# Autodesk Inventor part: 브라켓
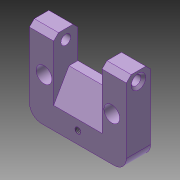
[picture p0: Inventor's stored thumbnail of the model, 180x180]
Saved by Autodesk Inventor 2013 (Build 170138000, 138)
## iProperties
Created: 2023-11
Part Number: 브라켓
Material: 강철, 연강
Document SubType Name: Modeling
Designer: mdu-01
Density: 1 g/cm^3
Author: mdu-01
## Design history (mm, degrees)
sketch "스케치1"
  geometry: L1 (0, 0)-(0, 10.407); L2 (-20, 5)-(-20, 34); L3 (-20, 34)-(-10, 34); L4 (-10, 34)-(-10, 20); L5 (20, 5)-(20, 34); L6 (20, 34)-(10, 34); L7 (10, 34)-(10, 20); L8 (-15, 0)-(15, 0); L9 (-10, 20)-(10, 20); A1 r 5 centre (-15, 5) between (-20, 5) and (-15, 0); A2 r 5 centre (15, 5) between (15, 0) and (20, 5); 2 further points
  constraints: 18 end point, 4 point on circle, 4 point on line, 4 symmetric about line, 4 tangent, 3 parallel, 2 centre point, 2 perpendicular, 1 equal radius, 1 horizontal alignment, 1 vertical
  dimensions: "d0" = 5 radius of A1; "d1" = 40 distance between parallel lines of L5 L2; "d2" = 34 distance between parallel lines of L3 L8; "d3" = 20 distance between parallel lines of L8 L9; "d4" = 20 distance between parallel lines of L7 L4
extrude "돌출1" new body sketch "스케치1" distance "d5" = 10; taper "d6" = 0 deg
sketch "스케치2"
  geometry: L1 (20, 0)-(20, 10) reference; L2 (34, 10)-(5, 10) reference; L3 (5, 10)-(0, 10) reference; L4 (0, 0)-(0, 10) reference; L5 (5, 0)-(34, 0) reference; L6 (5, 0)-(0, 0) reference; L7 (9, 10)-(20, 3.649)
  constraints: 2 end point, 2 point on line
  dimensions: "d7" = 30 deg angle of L7 L2; "d8" = 9 distance from line of L7.start L4
extrude "돌출2" cut sketch "스케치2" stored distance "d9" = 20; taper "d10" = 0 deg
hole "구멍1" diameter "d13" = 2.459; stored, may be unused: countersink angle "d17" = 90 deg, drill point angle "d19" = 118 deg; dims "d11" = 5, "d12" = 20, "d14" = 6, "d15" = 4, "d16" = 2, "d18" = 8
chamfer "모따기1" distance "d20" = 2; stored, may be unused: second distance "d21" = 2, angle "d22" = 45 deg
hole "구멍2" diameter "d25" = 4; stored, may be unused: countersink angle "d29" = 90 deg, drill point angle "d31" = 118 deg; dims "d23" = 4, "d24" = 5, "d26" = 6, "d27" = 4, "d28" = 2, "d30" = 8
sketch "스케치3"
  geometry: C1 r 1.23 at (-14, 18) reference; C2 r 1.23 at (14, 18) reference; 1 further point
hole "구멍3" sketch "스케치3" at (-14, 18), (14, 18) diameter "d32" = 3.4; stored, may be unused: countersink angle "d36" = 90 deg, drill point angle "d38" = 118 deg; dims "d33" = 6, "d34" = 6.5, "d35" = 6, "d37" = 8
chamfer "모따기2" distance "d39" = 1; stored, may be unused: second distance "d40" = 2, angle "d41" = 45 deg
node "솔리드1"
node "참조1"
node "참조2"
